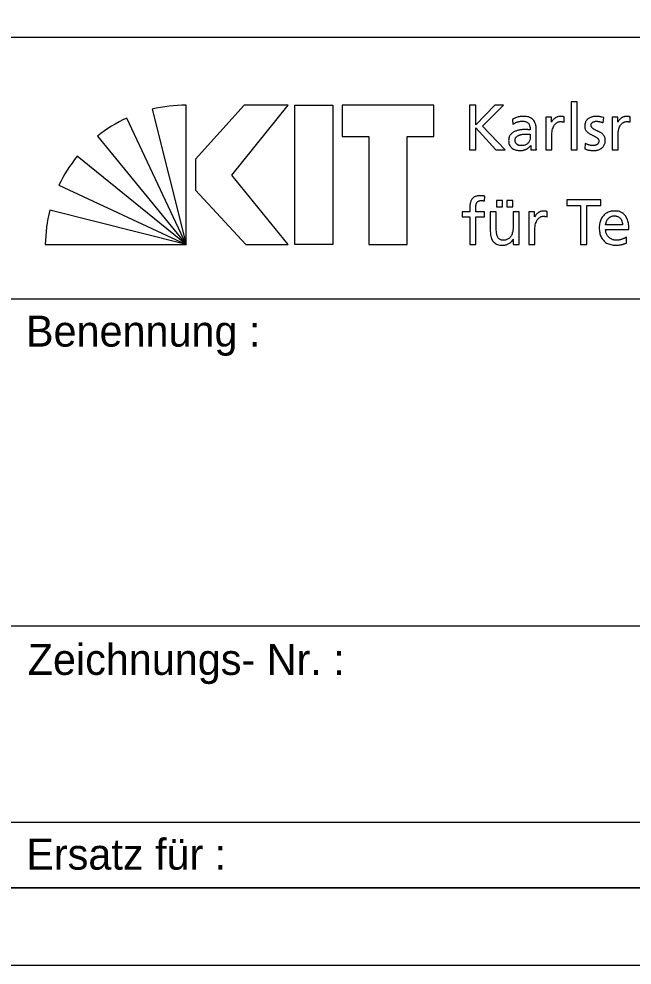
# Model space of a CAD drawing. Extents: x 0 to 594, y 0 to 420.
# Drawn here: x 550.33 to 570.16, y 0 to 30.58 of the extents above; entities that cross this region are included whole.
import ezdxf

# ---------------------------------------------------------------- set-up
doc = ezdxf.new("R2010")
doc.units = 0
doc.layers.add('90_Plankopf', color=7, linetype='Continuous')

msp = doc.modelspace()

# ---------------------------------------------------------------- linework, layer by layer
at = {"layer": '90_Plankopf'}
for p, q in [((503.06, 29.995), (592, 29.995)), ((503.06, 29.995), (592, 29.995)), ((554.637, 27.666), (555.74, 23.293)), ((555.74, 23.293), (555.74, 27.792)), ((564.905, 27.793), (564.905, 26.353)), ((555.74, 23.293), (553.817, 27.376)), ((566.29, 27.331), (566.3, 27.166)), ((567.963, 27.242), (567.963, 27.416)), ((569.228, 27.22), (569.245, 27.389)), ((570.106, 27.242), (570.106, 27.416)), ((567.059, 26.559), (567.059, 26.995)), ((552.872, 26.793), (555.74, 23.293)), ((566.865, 26.854), (566.865, 26.761)), ((564.905, 26.353), (565.111, 26.353)), ((565.753, 26.353), (566.054, 26.353)), ((568.649, 26.559), (568.638, 26.386)), ((555.74, 23.293), (552.217, 26.143)), ((551.62, 25.207), (555.74, 23.293)), ((565.387, 24.696), (565.395, 24.853)), ((555.74, 23.293), (551.329, 24.394)), ((567.413, 24.182), (567.413, 24.356)), ((569.853, 23.92), (569.308, 23.92)), ((569.308, 23.776), (570.059, 23.776)), ((551.182, 23.293), (555.74, 23.293)), ((569.979, 23.337), (569.979, 23.53)), ((550, 21.535), (592, 21.535)), ((550, 10.96), (592, 10.96)), ((550, 4.615), (592, 4.615)), ((592, 2.5), (503.06, 2.5)), ((508.9, 2.5), (592, 2.5)), ((508.9, 2.5), (592, 2.5))]:
    msp.add_line(p, q, dxfattribs=at)
for points in [[(0, 0), (594.5, 0), (594.5, 420.5), (0, 420.5)], [(12.5, 2.5), (592, 2.5), (592, 418), (12.5, 418)], [(559.033, 27.793), (557.618, 27.793), (556.036, 26.049), (556.036, 25.046), (557.669, 23.293), (559.042, 23.293), (557.211, 25.531)], [(560.485, 27.793), (560.485, 23.293), (559.251, 23.293), (559.251, 27.793)], [(560.781, 27.793), (560.781, 26.78), (561.651, 26.78), (561.651, 23.293), (562.885, 23.293), (562.885, 26.78), (563.755, 26.78), (563.755, 27.793)]]:
    msp.add_lwpolyline(points, close=True, dxfattribs=at)
for points in [[(568.19, 26.353), (568.384, 26.353), (568.384, 27.9), (568.19, 27.9), (568.19, 26.353)], [(566.054, 26.353), (565.324, 27.112), (566, 27.793), (565.726, 27.793), (565.111, 27.16), (565.111, 27.793), (564.905, 27.793)], [(567.561, 27.242), (567.557, 27.242), (567.557, 27.405), (567.375, 27.405), (567.375, 26.353), (567.569, 26.353), (567.569, 26.832)], [(569.703, 27.242), (569.699, 27.242), (569.699, 27.405), (569.518, 27.405), (569.518, 26.353), (569.712, 26.353), (569.712, 26.832)], [(565.111, 26.353), (565.111, 27.059), (565.753, 26.353)], [(566.882, 26.489), (566.886, 26.489), (566.886, 26.353), (567.067, 26.353)], [(565.777, 24.713), (565.777, 24.506), (565.971, 24.506), (565.971, 24.713), (565.777, 24.713)], [(566.115, 24.713), (566.115, 24.506), (566.309, 24.506), (566.309, 24.713), (566.115, 24.713)], [(568.495, 23.293), (568.701, 23.293), (568.701, 24.552), (569.149, 24.552), (569.149, 24.733), (568.047, 24.733), (568.047, 24.552), (568.495, 24.552), (568.495, 23.293)], [(564.912, 24.443), (564.912, 24.346), (564.665, 24.346), (564.665, 24.189), (564.912, 24.189), (564.912, 23.293), (565.106, 23.293), (565.106, 24.189), (565.385, 24.189), (565.385, 24.346), (565.106, 24.346), (565.106, 24.459)], [(565.771, 23.801), (565.771, 24.346), (565.577, 24.346), (565.577, 23.72)], [(566.507, 23.293), (566.507, 24.346), (566.313, 24.346), (566.313, 23.859)], [(567.011, 24.182), (567.007, 24.182), (567.007, 24.346), (566.825, 24.346), (566.825, 23.293), (567.019, 23.293), (567.019, 23.772)], [(566.316, 23.46), (566.32, 23.46), (566.32, 23.293), (566.507, 23.293)]]:
    msp.add_lwpolyline(points, dxfattribs=at)
for centre, start, end in [((555.724, 23.028), 89.8053, 103.1895), ((555.831, 23.059), 115.0126, 128.3968), ((555.908, 23.131), 140.7898, 154.174), ((555.946, 23.219), 165.7222, 179.1064)]:
    msp.add_arc(centre, 4.764, start, end, dxfattribs=at)
for points in [[(567.059, 26.995), (567.06, 27.09), (567.045, 27.17), (567.017, 27.235), (566.988, 27.3), (566.942, 27.348), (566.88, 27.381), (566.817, 27.413), (566.736, 27.43), (566.636, 27.43), (566.569, 27.43), (566.507, 27.42), (566.449, 27.402), (566.391, 27.384), (566.338, 27.361), (566.29, 27.331)], [(566.3, 27.166), (566.326, 27.188), (566.356, 27.207), (566.39, 27.223), (566.423, 27.239), (566.458, 27.251), (566.495, 27.26), (566.532, 27.269), (566.568, 27.273), (566.605, 27.273), (566.67, 27.273), (566.721, 27.263), (566.759, 27.243), (566.797, 27.222), (566.824, 27.191), (566.841, 27.151), (566.858, 27.11), (566.865, 27.059), (566.865, 26.999)], [(567.963, 27.416), (567.95, 27.418), (567.937, 27.421), (567.925, 27.423), (567.912, 27.425), (567.899, 27.427), (567.885, 27.428), (567.871, 27.429), (567.854, 27.43), (567.835, 27.43), (567.798, 27.43), (567.761, 27.422), (567.726, 27.406), (567.691, 27.39), (567.659, 27.368), (567.63, 27.339), (567.601, 27.311), (567.578, 27.279), (567.561, 27.242)], [(567.569, 26.832), (567.569, 26.92), (567.581, 26.996), (567.605, 27.06), (567.629, 27.124), (567.662, 27.174), (567.705, 27.208), (567.747, 27.243), (567.798, 27.26), (567.856, 27.261), (567.873, 27.261), (567.89, 27.26), (567.909, 27.257), (567.927, 27.254), (567.945, 27.249), (567.963, 27.242)], [(569.245, 27.389), (569.207, 27.4), (569.169, 27.41), (569.13, 27.418), (569.091, 27.426), (569.049, 27.43), (569.004, 27.43), (568.951, 27.43), (568.903, 27.423), (568.858, 27.41), (568.813, 27.397), (568.774, 27.377), (568.74, 27.35), (568.706, 27.323), (568.68, 27.29), (568.661, 27.249), (568.642, 27.208), (568.632, 27.161), (568.632, 27.106), (568.632, 27.064), (568.641, 27.028), (568.658, 26.997), (568.674, 26.966), (568.695, 26.94), (568.723, 26.917), (568.75, 26.895), (568.779, 26.875), (568.812, 26.857), (568.844, 26.84), (568.876, 26.824), (568.909, 26.809), (568.941, 26.793), (568.971, 26.777), (568.998, 26.761), (569.025, 26.745), (569.047, 26.727), (569.063, 26.706), (569.079, 26.686), (569.088, 26.663), (569.088, 26.636), (569.088, 26.607), (569.082, 26.584), (569.07, 26.564), (569.058, 26.545), (569.042, 26.529), (569.022, 26.518), (569.003, 26.506), (568.982, 26.498), (568.959, 26.493), (568.935, 26.487), (568.912, 26.485), (568.89, 26.485), (568.871, 26.485), (568.847, 26.488), (568.82, 26.493), (568.792, 26.499), (568.763, 26.507), (568.733, 26.518), (568.703, 26.529), (568.675, 26.543), (568.649, 26.559)], [(568.638, 26.386), (568.683, 26.363), (568.73, 26.347), (568.779, 26.339), (568.828, 26.331), (568.877, 26.327), (568.927, 26.328), (568.975, 26.328), (569.02, 26.335), (569.064, 26.348), (569.107, 26.361), (569.147, 26.381), (569.181, 26.408), (569.216, 26.435), (569.243, 26.469), (569.264, 26.51), (569.284, 26.551), (569.294, 26.6), (569.295, 26.656), (569.294, 26.704), (569.286, 26.745), (569.269, 26.778), (569.253, 26.811), (569.231, 26.84), (569.204, 26.863), (569.177, 26.886), (569.147, 26.906), (569.115, 26.922), (569.083, 26.939), (569.05, 26.954), (569.018, 26.968), (568.986, 26.983), (568.956, 26.998), (568.929, 27.013), (568.902, 27.029), (568.88, 27.047), (568.864, 27.068), (568.847, 27.089), (568.839, 27.115), (568.838, 27.145), (568.839, 27.174), (568.848, 27.198), (568.865, 27.217), (568.882, 27.236), (568.904, 27.25), (568.932, 27.259), (568.96, 27.269), (568.991, 27.273), (569.024, 27.273), (569.036, 27.273), (569.051, 27.271), (569.069, 27.269), (569.088, 27.266), (569.107, 27.261), (569.127, 27.256), (569.148, 27.251), (569.167, 27.246), (569.185, 27.239), (569.203, 27.233), (569.217, 27.226), (569.228, 27.22)], [(570.106, 27.416), (570.092, 27.418), (570.079, 27.421), (570.067, 27.423), (570.055, 27.425), (570.041, 27.427), (570.027, 27.428), (570.013, 27.429), (569.997, 27.43), (569.978, 27.43), (569.94, 27.43), (569.904, 27.422), (569.868, 27.406), (569.833, 27.39), (569.801, 27.368), (569.773, 27.339), (569.744, 27.311), (569.721, 27.279), (569.703, 27.242)], [(569.712, 26.832), (569.712, 26.92), (569.724, 26.996), (569.747, 27.06), (569.771, 27.124), (569.804, 27.174), (569.847, 27.208), (569.89, 27.243), (569.94, 27.26), (569.998, 27.261), (570.015, 27.261), (570.033, 27.26), (570.051, 27.257), (570.07, 27.254), (570.088, 27.249), (570.106, 27.242)], [(566.865, 26.999), (566.84, 27), (566.817, 27.001), (566.795, 27.001), (566.773, 27.002), (566.751, 27.003), (566.729, 27.003), (566.708, 27.003), (566.684, 27.003), (566.659, 27.003), (566.618, 27.003), (566.576, 26.999), (566.531, 26.992), (566.487, 26.985), (566.443, 26.973), (566.4, 26.957), (566.358, 26.941), (566.319, 26.919), (566.284, 26.892), (566.25, 26.866), (566.222, 26.833), (566.201, 26.794), (566.181, 26.755), (566.171, 26.709), (566.17, 26.656), (566.171, 26.58), (566.187, 26.518), (566.219, 26.469), (566.252, 26.421), (566.297, 26.385), (566.355, 26.362), (566.413, 26.339), (566.479, 26.328), (566.556, 26.328), (566.6, 26.328), (566.64, 26.334), (566.675, 26.344), (566.71, 26.355), (566.741, 26.368), (566.768, 26.384), (566.795, 26.401), (566.818, 26.419), (566.837, 26.437), (566.855, 26.455), (566.87, 26.472), (566.882, 26.489)], [(566.865, 26.761), (566.865, 26.709), (566.854, 26.661), (566.832, 26.62), (566.81, 26.578), (566.777, 26.546), (566.733, 26.522), (566.69, 26.498), (566.636, 26.485), (566.572, 26.485), (566.55, 26.485), (566.527, 26.489), (566.504, 26.496), (566.481, 26.503), (566.46, 26.514), (566.441, 26.529), (566.422, 26.543), (566.406, 26.561), (566.394, 26.582), (566.383, 26.604), (566.377, 26.628), (566.376, 26.656), (566.377, 26.693), (566.386, 26.724), (566.404, 26.749), (566.422, 26.773), (566.446, 26.793), (566.475, 26.807), (566.503, 26.822), (566.534, 26.833), (566.567, 26.841), (566.6, 26.848), (566.632, 26.853), (566.663, 26.855), (566.694, 26.858), (566.72, 26.859), (566.741, 26.858), (566.762, 26.858), (566.783, 26.858), (566.803, 26.856), (566.824, 26.855), (566.845, 26.855), (566.865, 26.854)], [(567.067, 26.353), (567.066, 26.363), (567.065, 26.377), (567.063, 26.393), (567.062, 26.411), (567.061, 26.433), (567.061, 26.46), (567.06, 26.486), (567.059, 26.52), (567.059, 26.559)], [(565.395, 24.853), (565.375, 24.856), (565.355, 24.859), (565.334, 24.862), (565.312, 24.864), (565.29, 24.866), (565.265, 24.866), (565.194, 24.865), (565.135, 24.855), (565.089, 24.836), (565.043, 24.816), (565.007, 24.787), (564.981, 24.75), (564.955, 24.713), (564.937, 24.668), (564.927, 24.616), (564.917, 24.565), (564.912, 24.507), (564.912, 24.443)], [(565.106, 24.459), (565.106, 24.495), (565.108, 24.528), (565.112, 24.558), (565.116, 24.588), (565.125, 24.615), (565.137, 24.637), (565.15, 24.66), (565.169, 24.677), (565.194, 24.69), (565.219, 24.702), (565.252, 24.709), (565.294, 24.709), (565.311, 24.709), (565.328, 24.708), (565.344, 24.706), (565.361, 24.703), (565.375, 24.7), (565.387, 24.696)], [(567.413, 24.356), (567.4, 24.359), (567.387, 24.361), (567.375, 24.363), (567.363, 24.365), (567.349, 24.367), (567.335, 24.368), (567.321, 24.37), (567.304, 24.37), (567.286, 24.37), (567.248, 24.37), (567.212, 24.362), (567.176, 24.346), (567.141, 24.33), (567.109, 24.308), (567.081, 24.28), (567.052, 24.252), (567.029, 24.219), (567.011, 24.182)], [(567.019, 23.772), (567.02, 23.86), (567.032, 23.937), (567.055, 24.001), (567.079, 24.065), (567.112, 24.114), (567.155, 24.148), (567.198, 24.183), (567.248, 24.201), (567.306, 24.201), (567.323, 24.201), (567.341, 24.2), (567.359, 24.197), (567.378, 24.195), (567.396, 24.19), (567.413, 24.182)], [(570.059, 23.776), (570.06, 23.861), (570.052, 23.94), (570.036, 24.012), (570.02, 24.084), (569.995, 24.146), (569.959, 24.2), (569.923, 24.254), (569.875, 24.295), (569.815, 24.325), (569.756, 24.355), (569.682, 24.37), (569.595, 24.37), (569.52, 24.37), (569.453, 24.357), (569.392, 24.331), (569.332, 24.305), (569.28, 24.269), (569.237, 24.221), (569.194, 24.174), (569.16, 24.118), (569.137, 24.052), (569.114, 23.988), (569.102, 23.916), (569.102, 23.838), (569.102, 23.752), (569.113, 23.674), (569.134, 23.604), (569.156, 23.535), (569.19, 23.475), (569.234, 23.425), (569.279, 23.375), (569.335, 23.336), (569.404, 23.309), (569.473, 23.282), (569.553, 23.269), (569.647, 23.268), (569.704, 23.269), (569.753, 23.273), (569.793, 23.28), (569.834, 23.288), (569.869, 23.297), (569.898, 23.307), (569.928, 23.317), (569.954, 23.327), (569.979, 23.337)], [(569.308, 23.92), (569.312, 23.955), (569.32, 23.989), (569.332, 24.024), (569.344, 24.058), (569.361, 24.089), (569.384, 24.118), (569.406, 24.147), (569.434, 24.17), (569.469, 24.187), (569.503, 24.204), (569.543, 24.213), (569.591, 24.213), (569.633, 24.213), (569.67, 24.206), (569.702, 24.19), (569.735, 24.175), (569.762, 24.154), (569.785, 24.127), (569.807, 24.101), (569.824, 24.069), (569.835, 24.034), (569.847, 23.999), (569.853, 23.961), (569.853, 23.92)], [(566.313, 23.859), (566.313, 23.794), (566.307, 23.736), (566.295, 23.683), (566.282, 23.63), (566.263, 23.584), (566.236, 23.546), (566.21, 23.507), (566.177, 23.478), (566.137, 23.457), (566.096, 23.436), (566.049, 23.426), (565.994, 23.425), (565.938, 23.429), (565.893, 23.444), (565.861, 23.473), (565.828, 23.501), (565.805, 23.542), (565.791, 23.597), (565.777, 23.651), (565.771, 23.719), (565.771, 23.801)], [(565.577, 23.72), (565.577, 23.626), (565.591, 23.545), (565.618, 23.478), (565.646, 23.41), (565.69, 23.359), (565.748, 23.323), (565.806, 23.287), (565.88, 23.269), (565.971, 23.268), (566.02, 23.269), (566.068, 23.276), (566.113, 23.291), (566.158, 23.307), (566.198, 23.329), (566.233, 23.357), (566.268, 23.386), (566.296, 23.42), (566.316, 23.46)], [(569.979, 23.53), (569.967, 23.521), (569.949, 23.51), (569.926, 23.497), (569.903, 23.485), (569.877, 23.474), (569.847, 23.463), (569.817, 23.452), (569.786, 23.443), (569.753, 23.436), (569.72, 23.429), (569.687, 23.426), (569.655, 23.425), (569.608, 23.426), (569.565, 23.434), (569.523, 23.451), (569.482, 23.468), (569.445, 23.492), (569.413, 23.523), (569.38, 23.554), (569.355, 23.59), (569.336, 23.633), (569.318, 23.676), (569.309, 23.724), (569.308, 23.776)]]:
    msp.add_open_spline(points, degree=3, dxfattribs=at)

# ---------------------------------------------------------------- texts
for s, p in [('Benennung :', (550.557, 19.989)), ('Zeichnungs- Nr. :', (550.614, 9.379)), ('Ersatz für :', (550.569, 3.084))]:
    msp.add_text(s, height=1, dxfattribs=at).set_placement(p)

doc.saveas('drawing.dxf')
